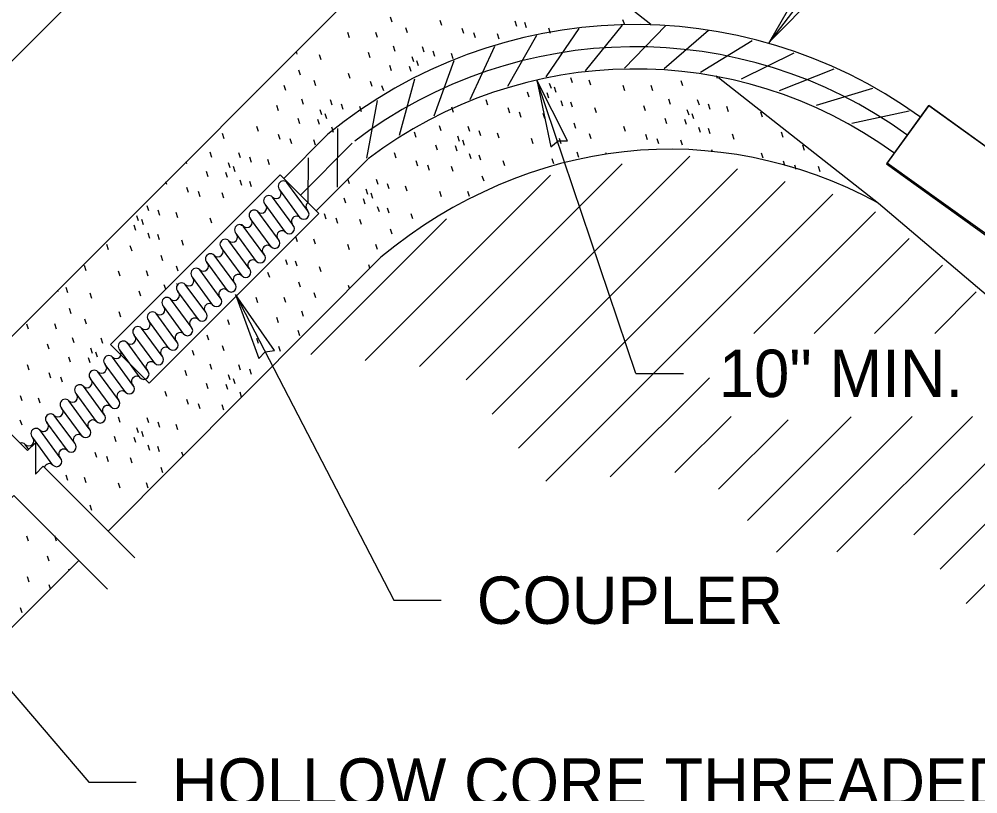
# Model space of a CAD drawing. Extents: x 99861 to 103151, y 100000 to 102076.
# Drawn here: x 100259.6 to 100583.5, y 100257.6 to 100519.2 of the extents above; entities that cross this region are included whole.
import ezdxf

# ---------------------------------------------------------------- set-up
doc = ezdxf.new("R2010")
doc.units = 0
for name, color, linetype in [('Level 1', 7, 'Continuous'), ('Level 10', 7, 'Continuous'), ('Level 15', 7, 'Continuous'), ('Level 2', 7, 'Continuous'), ('Level 20', 7, 'Continuous'), ('Level 4', 7, 'Continuous'), ('Level 6', 7, 'Continuous'), ('Level 8', 7, 'Continuous')]:
    doc.layers.add(name, color=color, linetype=linetype)

msp = doc.modelspace()

# ---------------------------------------------------------------- linework, layer by layer
at = {"layer": 'Level 1'}
for p, q in [((100349, 100465.48), (100363.98, 100480.47)), ((100377.45, 100472), (100359.95, 100454.54)), ((100357.01, 100454.64), (100350.08, 100464.09)), ((100352.1, 100449.73), (100345.17, 100459.18)), ((100354.55, 100452.18), (100347.62, 100461.63)), ((100349.64, 100447.27), (100342.71, 100456.72)), ((100347.19, 100444.81), (100340.26, 100454.26)), ((100334.68, 100450.05), (100334.56, 100449.43)), ((100342.27, 100439.89), (100335.34, 100449.34)), ((100344.73, 100442.35), (100337.81, 100451.8)), ((100339.82, 100437.44), (100332.89, 100446.88)), ((100337.36, 100434.98), (100330.44, 100444.43)), ((100332.45, 100430.07), (100325.52, 100439.52)), ((100334.9, 100432.52), (100327.97, 100441.97)), ((100330, 100427.6), (100323.07, 100437.06)), ((100327.53, 100425.14), (100320.6, 100434.59)), ((100312.97, 100429.97), (100312.73, 100429.67)), ((100325.08, 100422.68), (100318.15, 100432.13)), ((100320.16, 100417.78), (100313.24, 100427.22)), ((100322.63, 100420.23), (100315.7, 100429.68)), ((100317.71, 100415.32), (100310.78, 100424.76)), ((100315.26, 100412.86), (100308.33, 100422.31)), ((100310.34, 100407.94), (100303.41, 100417.39)), ((100312.79, 100410.39), (100305.87, 100419.85)), ((100307.89, 100405.48), (100300.96, 100414.93)), ((100305.43, 100403.02), (100298.5, 100412.47)), ((100300.52, 100398.11), (100293.59, 100407.56)), ((100302.97, 100400.57), (100296.05, 100410.02)), ((100298.07, 100395.65), (100291.13, 100405.1)), ((100295.61, 100393.19), (100288.68, 100402.64)), ((100290.7, 100388.28), (100283.76, 100397.72)), ((100293.15, 100390.73), (100286.22, 100400.18)), ((100288.24, 100385.82), (100281.31, 100395.27)), ((100285.78, 100383.36), (100278.85, 100392.81)), ((100280.87, 100378.45), (100273.94, 100387.9)), ((100283.32, 100380.91), (100276.39, 100390.36)), ((100278.41, 100375.99), (100271.48, 100385.44)), ((100275.96, 100373.53), (100269.02, 100382.98)), ((100271.04, 100368.61), (100264.11, 100378.06)), ((100273.5, 100371.07), (100266.57, 100380.52)), ((100262.89, 100373.91), (100261.65, 100375.6))]:
    msp.add_line(p, q, dxfattribs=at)
for points in [[(100564.02, 100486.16), (100563.76, 100486.35)], [(100555.28, 100474), (100555.07, 100474.15)]]:
    msp.add_lwpolyline(points, dxfattribs=at)
for centre, radius, start, end in [((100467.7, 100353.32), 164.08, 54.1697, 129.2321), ((100467.7, 100353.32), 149.1, 54.1279, 127.2134), ((100348.85, 100462.86), 1.74, 45.0187, 225.019), ((100343.94, 100457.94), 1.74, 45.0187, 225.019), ((100346.4, 100460.41), 1.74, 225.019, 45.0187), ((100341.49, 100455.49), 1.74, 225.019, 45.0187), ((100358.24, 100455.87), 1.74, 125.5022, 225.019), ((100339.03, 100453.03), 1.74, 45.0187, 225.019), ((100353.33, 100450.95), 1.74, 45.0187, 225.019), ((100355.79, 100453.41), 1.74, 225.019, 45.0187), ((100334.12, 100448.11), 1.74, 45.0187, 225.019), ((100336.57, 100450.57), 1.74, 225.019, 45.0187), ((100350.87, 100448.49), 1.74, 225.019, 45.0187), ((100331.66, 100445.65), 1.74, 225.019, 45.0187), ((100348.42, 100446.04), 1.74, 45.0187, 225.019), ((100329.2, 100443.2), 1.74, 45.0187, 225.019), ((100343.5, 100441.12), 1.74, 45.0187, 225.019), ((100345.96, 100443.58), 1.74, 225.019, 45.0187), ((100324.29, 100438.28), 1.74, 45.0187, 225.019), ((100326.75, 100440.74), 1.74, 225.019, 45.0187), ((100341.05, 100438.66), 1.74, 225.019, 45.0187), ((100321.83, 100435.82), 1.74, 225.019, 45.0187), ((100338.59, 100436.21), 1.74, 45.0187, 225.019), ((100319.38, 100433.36), 1.74, 45.0187, 225.019), ((100333.68, 100431.29), 1.74, 45.0187, 225.019), ((100336.14, 100433.75), 1.74, 225.019, 45.0187), ((100314.47, 100428.45), 1.74, 45.0187, 225.019), ((100316.92, 100430.91), 1.74, 225.019, 45.0187), ((100331.22, 100428.83), 1.74, 225.019, 45.0187), ((100312.01, 100425.99), 1.74, 225.019, 45.0187), ((100328.77, 100426.37), 1.74, 45.0187, 225.019), ((100309.55, 100423.53), 1.74, 45.0187, 225.019), ((100326.31, 100423.92), 1.74, 225.019, 45.0187), ((100304.64, 100418.62), 1.74, 45.0187, 225.019), ((100307.1, 100421.08), 1.74, 225.019, 45.0187), ((100321.4, 100419), 1.74, 225.019, 45.0187), ((100323.85, 100421.46), 1.74, 45.0187, 225.019), ((100302.18, 100416.16), 1.74, 225.019, 45.0187), ((100318.94, 100416.54), 1.74, 45.0187, 225.019), ((100299.73, 100413.7), 1.74, 45.0187, 225.019), ((100316.49, 100414.08), 1.74, 225.019, 45.0187), ((100294.82, 100408.79), 1.74, 45.0187, 225.019), ((100297.27, 100411.24), 1.74, 225.019, 45.0187), ((100311.57, 100409.17), 1.74, 225.019, 45.0187), ((100314.03, 100411.63), 1.74, 45.0187, 225.019), ((100292.36, 100406.33), 1.74, 225.019, 45.0187), ((100309.12, 100406.71), 1.74, 45.0187, 225.019), ((100289.9, 100403.87), 1.74, 45.0187, 225.019), ((100306.66, 100404.25), 1.74, 225.019, 45.0187), ((100284.99, 100398.95), 1.74, 45.0187, 225.019), ((100287.45, 100401.41), 1.74, 225.019, 45.0187), ((100304.2, 100401.79), 1.74, 45.0187, 225.019), ((100282.53, 100396.5), 1.74, 225.019, 45.0187), ((100299.29, 100396.88), 1.74, 45.0187, 225.019), ((100301.75, 100399.34), 1.74, 225.019, 45.0187), ((100280.08, 100394.04), 1.74, 45.0187, 225.019), ((100296.83, 100394.42), 1.74, 225.019, 45.0187), ((100277.62, 100391.58), 1.74, 225.019, 45.0187), ((100294.38, 100391.96), 1.74, 45.0187, 225.019), ((100272.71, 100386.66), 1.74, 225.019, 45.0187), ((100275.16, 100389.12), 1.74, 45.0187, 225.019), ((100289.47, 100387.05), 1.74, 45.0187, 225.019), ((100291.92, 100389.5), 1.74, 225.019, 45.0187), ((100270.25, 100384.21), 1.74, 45.0187, 225.019), ((100270.25, 100384.21), 1.74, 45.0187, 80.596), ((100287.01, 100384.59), 1.74, 225.019, 45.0187), ((100267.8, 100381.75), 1.74, 225.019, 45.0187), ((100284.55, 100382.13), 1.74, 45.0187, 225.019), ((100262.88, 100376.83), 1.74, 225.019, 45.0187), ((100265.34, 100379.29), 1.74, 45.0187, 225.019), ((100265.34, 100379.29), 1.74, 45.0187, 225.019), ((100267.8, 100381.75), 1.74, 225.019, 283.6866), ((100279.64, 100377.21), 1.74, 104.5768, 225.019), ((100279.64, 100377.21), 1.74, 45.0187, 144.2258), ((100282.1, 100379.67), 1.74, 225.019, 45.0187), ((100260.43, 100374.37), 1.74, 45.0187, 105.1761), ((100277.18, 100374.76), 1.74, 225.019, 45.0187), ((100274.73, 100372.3), 1.74, 45.0187, 225.019), ((100274.73, 100372.3), 1.74, 104.5768, 225.019), ((100269.82, 100367.38), 1.74, 45.0187, 164.6481), ((100272.27, 100369.84), 1.74, 225.019, 45.0187)]:
    msp.add_arc(centre, radius, start, end, dxfattribs=at)
at = {"layer": 'Level 10'}
for p, q in [((100410.64, 100397.43), (100486.21, 100472.99)), ((100394.84, 100401.99), (100463.28, 100470.43)), ((100394.84, 100401.99), (100463.28, 100470.43)), ((100419.45, 100385.87), (100502.28, 100468.71)), ((100376.48, 100404), (100439.09, 100466.61)), ((100428.26, 100374.32), (100518.36, 100464.42)), ((100428.26, 100374.32), (100518.36, 100464.42)), ((100437.49, 100363.18), (100534.44, 100460.13)), ((100507.8, 100413.13), (100548.88, 100454.21)), ((100358.13, 100406.01), (100403.96, 100451.84)), ((100528.17, 100413.13), (100560.22, 100445.18)), ((100528.17, 100413.13), (100560.22, 100445.18)), ((100548.53, 100413.13), (100571.56, 100436.16)), ((100568.9, 100413.13), (100582.91, 100427.14)), ((100459.31, 100364.64), (100492.81, 100398.14)), ((100570.68, 100333.46), (100628.28, 100391.06)), ((100481.13, 100366.09), (100500.14, 100385.1)), ((100481.13, 100366.09), (100500.14, 100385.1)), ((100505.64, 100349.88), (100540.67, 100384.91)), ((100515.39, 100339.26), (100561.23, 100385.1)), ((100515.39, 100339.26), (100561.23, 100385.1)), ((100535.86, 100339.36), (100581.6, 100385.1)), ((100561.88, 100345.03), (100601.96, 100385.1)), ((100495.89, 100360.49), (100519.33, 100383.93)), ((100579.48, 100321.9), (100639.62, 100382.04))]:
    msp.add_line(p, q, dxfattribs=at)
at = {"layer": 'Level 15'}
for p, q in [((100370.21, 100618.21), (100044.49, 100292.32)), ((100584, 100605), (100512.76, 100511.1)), ((100467.98, 100399.61), (100434.45, 100498.67)), ((100332.7, 100426.22), (100386.22, 100323.01)), ((100467.98, 100399.61), (100483.98, 100399.61)), ((100229.29, 100324.37), (100283.19, 100261.59)), ((100386.22, 100323.01), (100402.22, 100323.01)), ((100283.19, 100261.59), (100299.19, 100261.59))]:
    msp.add_line(p, q, dxfattribs=at)
for points in [[(100513.24, 100511.74), (100524.66, 100531.73), (100526.4, 100529.08), (100529.42, 100528.12)], [(100434.45, 100498.67), (100439.22, 100476.14), (100441.69, 100478.13), (100444.85, 100478.13)], [(100332.7, 100426.22), (100340.56, 100404.58), (100342.72, 100406.89), (100345.86, 100407.33)]]:
    msp.add_lwpolyline(points, close=True, dxfattribs=at)
for points in [[(100232.12, 100403.88), (100262.49, 100373.51), (100265.12, 100376.14), (100265.12, 100365.62), (100267.75, 100368.25), (100298.73, 100337.26)], [(100222.4, 100393.85), (100252.59, 100363.66), (100255.22, 100366.28), (100255.22, 100355.77), (100257.84, 100358.4), (100289.49, 100326.75)]]:
    msp.add_lwpolyline(points, dxfattribs=at)
at = {"layer": 'Level 2'}
for p, q in [((100552.84, 100470.62), (100566.86, 100490.1)), ((100566.86, 100490.1), (100613.34, 100456.68)), ((100599.33, 100437.2), (100552.84, 100470.62)), ((100290.46, 100409.39), (100347.77, 100466.71)), ((100347.77, 100466.71), (100360.89, 100453.6)), ((100360.89, 100453.6), (100303.56, 100396.28)), ((100303.56, 100396.28), (100290.46, 100409.39))]:
    msp.add_line(p, q, dxfattribs=at)
for points in [[(100240.46, 100395.54), (100414.92, 100569.98)], [(100422.41, 100557.25), (100473.01, 100517.51)], [(100495.89, 100499.54), (100549.91, 100457.1)], [(100549.91, 100457.1), (100654.66, 100368.29), (100709.41, 100337.34), (100740.32, 100314.17), (100760.67, 100302.17), (100798.98, 100271.91), (100808.43, 100266.08), (100871.82, 100220.81), (100988.21, 100150.42)], [(100381.8, 100438.88), (100289.68, 100346.31)], [(100279.81, 100336.43), (100140.17, 100196.7), (100090.93, 100245.91), (100230.59, 100385.66)]]:
    msp.add_lwpolyline(points, dxfattribs=at)
msp.add_ellipse((100479.4, 100250.59), major_axis=(0, 224.72), ratio=0.795647, start_param=5.877818, end_param=6.86059, dxfattribs=at)
at = {"layer": 'Level 4'}
for p, q in [((100448.73, 100516.06), (100437.53, 100499.73)), ((100463.3, 100517.16), (100450.76, 100501.83)), ((100477.91, 100516.95), (100464.13, 100502.74)), ((100492.46, 100515.45), (100477.52, 100502.46)), ((100434.32, 100513.67), (100424.54, 100496.46)), ((100507.27, 100511.92), (100489.74, 100501.25)), ((100420.18, 100510.02), (100411.89, 100492.04)), ((100521.25, 100507.77), (100503.53, 100498.94)), ((100406.42, 100505.12), (100399.68, 100486.5)), ((100534.8, 100502.39), (100516.4, 100495.09)), ((100393.16, 100499.02), (100388.02, 100479.9)), ((100547.82, 100495.83), (100528.87, 100490.11)), ((100380.5, 100491.77), (100376.99, 100472.29)), ((100560.21, 100488.14), (100540.84, 100484.04)), ((100367.19, 100462.46), (100367.21, 100482.26)), ((100372.16, 100477.31), (100354.66, 100459.85)), ((100357.28, 100457.49), (100357.3, 100472.37)), ((100349, 100465.48), (100359.95, 100454.54))]:
    msp.add_line(p, q, dxfattribs=at)
msp.add_lwpolyline([(100559.65, 100480.09), (100559.42, 100480.26)], dxfattribs=at)
msp.add_arc((100467.7, 100353.32), 156.6, 54.1279, 127.2134, dxfattribs=at)
at = {"layer": 'Level 6'}
msp.add_lwpolyline([(100599.12, 100436.91), (100613.34, 100456.68), (100566.86, 100490.1), (100552.64, 100470.34)], close=True, dxfattribs=at)
at = {"layer": 'Level 8'}
for p, q in [((100385.63, 100518.19), (100385.06, 100519.93)), ((100402.45, 100517.07), (100401.88, 100518.82)), ((100427.77, 100516.77), (100427.2, 100518.52)), ((100431.05, 100516.34), (100430.48, 100518.09)), ((100464.17, 100517.28), (100463.59, 100519.02)), ((100371.23, 100512.97), (100370.66, 100514.72)), ((100380.69, 100513.01), (100380.11, 100514.76)), ((100390.84, 100514.62), (100390.27, 100516.36)), ((100409.82, 100514.36), (100409.25, 100516.11)), ((100413.74, 100512.93), (100413.17, 100514.67)), ((100421.73, 100512.5), (100421.15, 100514.25)), ((100439.12, 100514.42), (100438.55, 100516.17)), ((100353.55, 100507.41), (100353.25, 100508.32)), ((100378.24, 100506.19), (100377.67, 100507.93)), ((100386.67, 100508.34), (100386.1, 100510.09)), ((100396.39, 100508.15), (100395.81, 100509.9)), ((100400.08, 100506.65), (100399.51, 100508.4)), ((100406.21, 100505.87), (100405.64, 100507.62)), ((100361.62, 100505.49), (100361.05, 100507.24)), ((100392.89, 100504.78), (100392.32, 100506.52)), ((100394.56, 100503.47), (100393.99, 100505.22)), ((100354.63, 100500.29), (100354.06, 100502.04)), ((100385.41, 100501.81), (100384.84, 100503.56)), ((100392.04, 100501.56), (100391.47, 100503.3)), ((100359.84, 100496.72), (100359.27, 100498.47)), ((100371.46, 100499.17), (100370.89, 100500.92)), ((100378.83, 100496.46), (100378.26, 100498.21)), ((100446.58, 100497.69), (100446.01, 100499.44)), ((100452.71, 100496.91), (100452.14, 100498.65)), ((100483.84, 100496.7), (100483.27, 100498.44)), ((100495.46, 100499.15), (100495.14, 100500.13)), ((100340.24, 100495.08), (100340.18, 100495.25)), ((100349.69, 100495.12), (100349.12, 100496.86)), ((100382.75, 100495.03), (100382.18, 100496.78)), ((100431.91, 100492.85), (100431.34, 100494.6)), ((100439.39, 100495.81), (100438.82, 100497.56)), ((100441.07, 100494.51), (100440.49, 100496.26)), ((100464.23, 100495.05), (100463.66, 100496.79)), ((100473.69, 100495.09), (100473.12, 100496.84)), ((100355.68, 100490.45), (100355.1, 100492.19)), ((100365.39, 100490.25), (100364.82, 100492)), ((100417.96, 100490.21), (100417.39, 100491.96)), ((100438.54, 100492.59), (100437.97, 100494.34)), ((100443.28, 100489.91), (100442.71, 100491.66)), ((100479.67, 100490.42), (100479.1, 100492.17)), ((100489.39, 100490.23), (100488.81, 100491.97)), ((100347.25, 100488.29), (100346.68, 100490.04)), ((100361.89, 100486.88), (100361.32, 100488.63)), ((100369.08, 100488.76), (100368.51, 100490.51)), ((100375.22, 100487.97), (100374.65, 100489.72)), ((100406.34, 100487.76), (100405.77, 100489.51)), ((100425.33, 100487.5), (100424.76, 100489.25)), ((100446.55, 100489.48), (100445.98, 100491.23)), ((100454.62, 100487.57), (100454.05, 100489.31)), ((100471.24, 100488.26), (100470.67, 100490.01)), ((100485.89, 100486.85), (100485.32, 100488.6)), ((100493.08, 100488.73), (100492.51, 100490.48)), ((100499.21, 100487.95), (100498.64, 100489.69)), ((100354.42, 100483.92), (100353.84, 100485.66)), ((100361.04, 100483.66), (100360.47, 100485.41)), ((100363.57, 100485.58), (100363, 100487.32)), ((100429.25, 100486.07), (100428.68, 100487.82)), ((100437.23, 100485.65), (100436.66, 100487.39)), ((100478.41, 100483.89), (100477.84, 100485.64)), ((100485.04, 100483.63), (100484.47, 100485.38)), ((100487.57, 100485.55), (100486.99, 100487.3)), ((100510.73, 100486.09), (100510.16, 100487.83)), ((100340.46, 100481.28), (100339.89, 100483.03)), ((100365.78, 100480.98), (100365.21, 100482.73)), ((100402.18, 100481.49), (100401.6, 100483.23)), ((100411.89, 100481.29), (100411.32, 100483.04)), ((100447.64, 100482.37), (100447.06, 100484.12)), ((100464.46, 100481.25), (100463.89, 100483)), ((100489.78, 100480.95), (100489.21, 100482.7)), ((100493.05, 100480.52), (100492.48, 100482.27)), ((100328.85, 100478.83), (100328.28, 100480.57)), ((100347.83, 100478.57), (100347.26, 100480.32)), ((100351.75, 100477.14), (100351.18, 100478.88)), ((100359.74, 100476.71), (100359.16, 100478.46)), ((100393.75, 100479.33), (100393.18, 100481.08)), ((100408.39, 100477.92), (100407.82, 100479.67)), ((100415.58, 100479.8), (100415.01, 100481.54)), ((100421.72, 100479.01), (100421.15, 100480.76)), ((100433.24, 100477.15), (100432.67, 100478.9)), ((100442.69, 100477.19), (100442.12, 100478.94)), ((100452.84, 100478.8), (100452.27, 100480.55)), ((100471.83, 100478.54), (100471.26, 100480.29)), ((100475.75, 100477.11), (100475.18, 100478.86)), ((100483.73, 100476.69), (100483.16, 100478.43)), ((100501.13, 100478.6), (100500.55, 100480.35)), ((100517.75, 100479.3), (100517.17, 100481.05)), ((100400.92, 100474.96), (100400.35, 100476.7)), ((100407.55, 100474.7), (100406.97, 100476.45)), ((100410.07, 100476.62), (100409.5, 100478.36)), ((100493.82, 100474.38), (100493.56, 100475.16)), ((100524.91, 100474.93), (100524.34, 100476.68)), ((100324.68, 100472.55), (100324.11, 100474.3)), ((100334.4, 100472.36), (100333.82, 100474.11)), ((100338.09, 100470.86), (100337.52, 100472.61)), ((100386.96, 100472.32), (100386.39, 100474.06)), ((100412.28, 100472.02), (100411.71, 100473.77)), ((100415.56, 100471.59), (100414.99, 100473.33)), ((100440.25, 100470.37), (100439.68, 100472.11)), ((100448.68, 100472.53), (100448.11, 100474.27)), ((100457.97, 100473.62), (100457.82, 100474.08)), ((100510.96, 100472.29), (100510.39, 100474.04)), ((100316.25, 100470.4), (100316.02, 100471.1)), ((100330.9, 100468.99), (100330.33, 100470.73)), ((100332.57, 100467.68), (100332, 100469.43)), ((100344.22, 100470.08), (100343.65, 100471.83)), ((100394.33, 100469.61), (100393.76, 100471.35)), ((100398.25, 100468.18), (100397.68, 100469.92)), ((100406.24, 100467.75), (100405.66, 100469.5)), ((100423.63, 100469.67), (100423.06, 100471.42)), ((100518.23, 100469.87), (100517.76, 100471.33)), ((100522.13, 100468.52), (100521.68, 100469.89)), ((100530.23, 100467.73), (100529.66, 100469.47)), ((100323.42, 100466.02), (100322.85, 100467.77)), ((100330.05, 100465.77), (100329.48, 100467.51)), ((100416.64, 100464.48), (100416.07, 100466.22)), ((100309.47, 100463.38), (100309.18, 100464.26)), ((100316.84, 100460.67), (100316.27, 100462.42)), ((100334.79, 100463.09), (100334.22, 100464.83)), ((100338.06, 100462.65), (100337.49, 100464.4)), ((100371.18, 100463.59), (100370.61, 100465.34)), ((100380.9, 100463.4), (100380.32, 100465.14)), ((100384.59, 100461.9), (100384.02, 100463.65)), ((100390.72, 100461.12), (100390.15, 100462.86)), ((100320.76, 100459.24), (100320.19, 100460.99)), ((100328.74, 100458.82), (100328.17, 100460.57)), ((100377.4, 100460.02), (100376.83, 100461.77)), ((100379.08, 100458.72), (100378.5, 100460.47)), ((100402.24, 100459.26), (100401.67, 100461)), ((100411.7, 100459.3), (100411.13, 100461.05)), ((100303.4, 100454.46), (100302.83, 100456.21)), ((100369.92, 100457.06), (100369.35, 100458.81)), ((100376.55, 100456.8), (100375.98, 100458.55)), ((100381.29, 100454.12), (100380.72, 100455.87)), ((100299.9, 100451.09), (100299.33, 100452.84)), ((100307.09, 100452.97), (100306.52, 100454.72)), ((100313.23, 100452.18), (100312.66, 100453.93)), ((100363.34, 100451.71), (100362.77, 100453.46)), ((100384.56, 100453.69), (100383.99, 100455.44)), ((100392.63, 100451.78), (100392.06, 100453.52)), ((100299.05, 100447.87), (100298.48, 100449.62)), ((100301.58, 100449.79), (100301.01, 100451.53)), ((100324.75, 100450.32), (100324.18, 100452.07)), ((100367.26, 100450.28), (100366.69, 100452.03)), ((100375.24, 100449.86), (100374.67, 100451.6)), ((100303.79, 100445.19), (100303.22, 100446.94)), ((100307.07, 100444.76), (100306.5, 100446.51)), ((100385.65, 100446.58), (100385.07, 100448.33)), ((100289.76, 100441.35), (100289.19, 100443.09)), ((100315.14, 100442.84), (100314.57, 100444.59)), ((100353.59, 100444.01), (100353.03, 100445.74)), ((100359.73, 100443.22), (100359.16, 100444.97)), ((100371.25, 100441.36), (100370.68, 100443.11)), ((100380.7, 100441.4), (100380.13, 100443.15)), ((100297.75, 100440.92), (100297.17, 100442.67)), ((100308.15, 100437.65), (100307.58, 100439.39)), ((100350.29, 100436.23), (100349.72, 100437.98)), ((100353.57, 100435.8), (100353, 100437.54)), ((100378.08, 100435.14), (100377.69, 100436.32)), ((100282.23, 100434.29), (100281.66, 100436.04)), ((100293.75, 100432.43), (100293.18, 100434.18)), ((100303.21, 100432.47), (100302.64, 100434.22)), ((100313.36, 100434.08), (100312.79, 100435.82)), ((100344.25, 100431.96), (100343.67, 100433.71)), ((100361.64, 100433.88), (100361.07, 100435.63)), ((100354.65, 100428.69), (100354.08, 100430.43)), ((100272.8, 100427.3), (100272.66, 100427.73)), ((100276.07, 100426.86), (100275.5, 100428.61)), ((100284.14, 100424.95), (100283.57, 100426.69)), ((100300.76, 100425.64), (100300.19, 100427.39)), ((100309.11, 100428.05), (100308.62, 100429.55)), ((100359.86, 100425.12), (100359.29, 100426.86)), ((100371.25, 100428.27), (100370.9, 100429.31)), ((100340.25, 100423.47), (100339.68, 100425.21)), ((100349.71, 100423.51), (100349.14, 100425.26)), ((100277.15, 100419.75), (100276.58, 100421.5)), ((100293.98, 100418.63), (100293.41, 100420.38)), ((100355.69, 100418.84), (100355.12, 100420.59)), ((100282.36, 100416.18), (100281.79, 100417.93)), ((100330.64, 100415.99), (100330.07, 100417.73)), ((100347.26, 100416.68), (100346.69, 100418.43)), ((100262.76, 100414.53), (100262.19, 100416.28)), ((100272.21, 100414.58), (100271.64, 100416.32)), ((100354.43, 100412.31), (100353.86, 100414.06)), ((100278.2, 100409.91), (100277.62, 100411.65)), ((100287.91, 100409.71), (100287.34, 100411.46)), ((100323.65, 100410.79), (100323.08, 100412.54)), ((100340.48, 100409.67), (100339.91, 100411.42)), ((100269.77, 100407.75), (100269.2, 100409.5)), ((100284.41, 100406.34), (100283.84, 100408.09)), ((100291.6, 100408.22), (100291.59, 100408.26)), ((100318.71, 100405.61), (100318.14, 100407.36)), ((100328.86, 100407.22), (100328.29, 100408.97)), ((100347.85, 100406.96), (100347.28, 100408.71)), ((100276.94, 100403.38), (100276.37, 100405.12)), ((100283.57, 100403.12), (100282.99, 100404.87)), ((100286.09, 100405.04), (100285.52, 100406.78)), ((100262.98, 100400.74), (100262.41, 100402.48)), ((100324.7, 100400.95), (100324.12, 100402.69)), ((100334.41, 100400.75), (100333.84, 100402.5)), ((100338.1, 100399.26), (100337.53, 100401)), ((100270.35, 100398.03), (100269.78, 100399.77)), ((100274.27, 100396.6), (100273.7, 100398.34)), ((100316.27, 100398.79), (100315.7, 100400.53)), ((100330.91, 100397.38), (100330.34, 100399.12)), ((100332.59, 100396.07), (100332.02, 100397.82)), ((100323.44, 100394.42), (100322.87, 100396.16)), ((100330.07, 100394.16), (100329.49, 100395.9)), ((100260.61, 100390.32), (100260.04, 100392.07)), ((100266.74, 100389.54), (100266.17, 100391.28)), ((100309.49, 100391.78), (100308.91, 100393.52)), ((100334.76, 100391.61), (100334.23, 100393.22)), ((100316.85, 100389.07), (100316.28, 100390.81)), ((100320.78, 100387.63), (100320.2, 100389.38)), ((100328.76, 100387.21), (100328.19, 100388.96)), ((100293.7, 100383.05), (100293.13, 100384.8)), ((100303.42, 100382.86), (100302.84, 100384.6)), ((100260.58, 100382.11), (100260.01, 100383.86)), ((100299.92, 100379.48), (100299.35, 100381.23)), ((100307.11, 100381.36), (100306.54, 100383.11)), ((100313.24, 100380.58), (100312.67, 100382.32)), ((100292.44, 100376.52), (100291.87, 100378.27)), ((100299.07, 100376.26), (100298.5, 100378.01)), ((100301.6, 100378.18), (100301.02, 100379.93)), ((100303.81, 100373.58), (100303.24, 100375.33)), ((100307.08, 100373.15), (100306.51, 100374.9)), ((100285.86, 100371.17), (100285.29, 100372.92)), ((100314.99, 100371.74), (100314.58, 100372.98)), ((100289.78, 100369.74), (100289.21, 100371.49)), ((100297.76, 100369.32), (100297.19, 100371.06)), ((100276.11, 100363.47), (100275.54, 100365.21)), ((100308.17, 100366.04), (100307.59, 100367.79)), ((100282.25, 100362.68), (100281.68, 100364.43)), ((100293.77, 100360.82), (100293.2, 100362.57)), ((100303.22, 100360.86), (100302.65, 100362.61)), ((100284.16, 100353.34), (100283.59, 100355.09)), ((100262.77, 100342.93), (100262.2, 100344.67)), ((100272.23, 100342.97), (100271.66, 100344.71)), ((100269.78, 100336.14), (100269.21, 100337.89)), ((100276.51, 100333.13), (100276.38, 100333.52)), ((100263, 100329.13), (100262.43, 100330.88)), ((100270.23, 100326.85), (100269.8, 100328.17)), ((100260.62, 100318.72), (100260.05, 100320.46))]:
    msp.add_line(p, q, dxfattribs=at)

# ---------------------------------------------------------------- texts
at = {"layer": 'Level 20'}
for s, p in [('10" MIN. R.', (100495.98, 100391.61)), ('COUPLER', (100414.22, 100315.01)), ('HOLLOW CORE THREADED BAR', (100311.19, 100253.59))]:
    msp.add_text(s, height=16, dxfattribs=at).set_placement(p)

doc.saveas('drawing.dxf')
